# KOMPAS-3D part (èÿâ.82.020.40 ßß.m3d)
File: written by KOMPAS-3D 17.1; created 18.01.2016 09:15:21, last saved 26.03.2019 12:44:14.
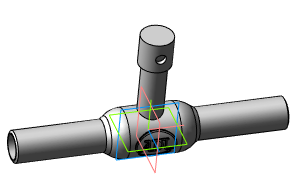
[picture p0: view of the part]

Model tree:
1. Операция без истории:5  (labels: Сталь 20  ГОСТ 1050-88)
